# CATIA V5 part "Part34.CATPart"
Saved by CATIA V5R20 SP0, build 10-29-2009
Part number: VA 161320-3 COMPRIMIDO
Revision: ANY
Definition: UNKNOWN
Nomenclature: VA 161320-3 COMPRIMIDO
Source: Unknown
Bounding box of the stored display mesh (mm): x -5.25 to 5.25, y 0 to 5.8, z -5.25 to 5.25
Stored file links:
  C:\Users\Utente\Desktop\IO LAVORO\3D X SITO CF\CUMSA\3D files VA\VA 201720\Part34.CATPart
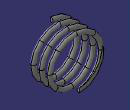
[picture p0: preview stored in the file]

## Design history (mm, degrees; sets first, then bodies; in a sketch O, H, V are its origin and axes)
Body1 "Cortar-Extruir1" (main body)
  Solid1: solid without history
